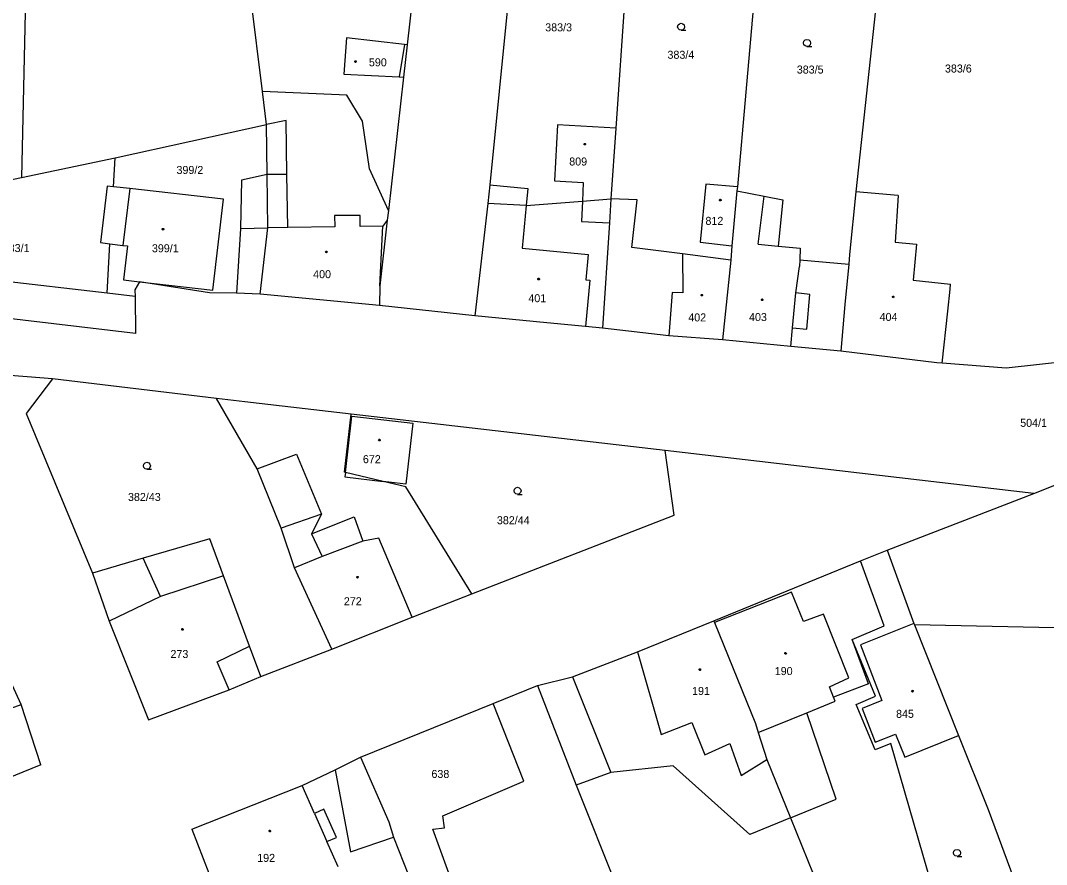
# Model space of a CAD drawing. Extents: x -757994 to -755874, y -1047691 to -1046119.
# Drawn here: x -757748.9 to -757640, y -1047070.2 to -1046980.7 of the extents above; entities that cross this region are included whole.
import ezdxf

# ---------------------------------------------------------------- set-up
doc = ezdxf.new("R2010")
doc.units = 0
doc.layers.add('katastrální mapa', color=7, linetype='Continuous')

msp = doc.modelspace()

# ---------------------------------------------------------------- linework, layer by layer
at = {"layer": 'katastrální mapa'}
for p, q in [((-757746.63, -1046900.81), (-757748.84, -1046997.32)), ((-757723.24, -1046988.2), (-757726.54, -1046961.83)), ((-757705.82, -1046964.85), (-757707.89, -1046983.24)), ((-757695.92, -1046966.36), (-757699.11, -1046998.09)), ((-757684.03, -1046967.9), (-757685.73, -1046992.09)), ((-757670.33, -1046970.08), (-757672.82, -1046998.32)), ((-757657.21, -1046970.65), (-757660.23, -1046998.82)), ((-757714.32, -1046982.5), (-757714.61, -1046986.34)), ((-757708.17, -1046983.21), (-757714.32, -1046982.5)), ((-757708.17, -1046983.21), (-757708.74, -1046986.64)), ((-757707.89, -1046983.24), (-757708.28, -1046986.66)), ((-757707.89, -1046983.24), (-757708.17, -1046983.21)), ((-757714.61, -1046986.34), (-757708.74, -1046986.64)), ((-757708.28, -1046986.66), (-757709.87, -1047000.8)), ((-757708.74, -1046986.64), (-757708.28, -1046986.66)), ((-757714.27, -1046988.59), (-757723.24, -1046988.2)), ((-757722.81, -1046991.67), (-757723.24, -1046988.2)), ((-757712.62, -1046991.35), (-757714.27, -1046988.59)), ((-757720.71, -1046991.28), (-757722.81, -1046991.67)), ((-757720.64, -1046996.98), (-757720.71, -1046991.28)), ((-757738.88, -1046995.22), (-757722.81, -1046991.67)), ((-757722.74, -1046997.01), (-757722.81, -1046991.67)), ((-757711.86, -1046996.41), (-757712.62, -1046991.35)), ((-757691.91, -1046991.73), (-757692.25, -1046997.66)), ((-757685.73, -1046992.09), (-757691.91, -1046991.73)), ((-757685.73, -1046992.09), (-757686.25, -1046999.57)), ((-757748.84, -1046997.32), (-757738.88, -1046995.22)), ((-757739.07, -1046998.31), (-757738.88, -1046995.22)), ((-757709.87, -1047000.8), (-757711.86, -1046996.41)), ((-757768.4, -1047001.45), (-757748.84, -1046997.32)), ((-757725.46, -1046997.59), (-757725.56, -1047002.71)), ((-757722.74, -1046997.01), (-757725.46, -1046997.59)), ((-757720.64, -1046996.98), (-757722.74, -1046997.01)), ((-757722.66, -1047002.66), (-757722.74, -1046997.01)), ((-757720.56, -1047002.63), (-757720.64, -1046996.98)), ((-757692.25, -1046997.66), (-757689.18, -1046997.84)), ((-757739.72, -1046998.25), (-757740.43, -1047004.2)), ((-757739.07, -1046998.31), (-757739.72, -1046998.25)), ((-757737.34, -1046998.49), (-757739.07, -1046998.31)), ((-757737.34, -1046998.49), (-757738.06, -1047004.52)), ((-757727.39, -1046999.6), (-757737.34, -1046998.49)), ((-757699.11, -1046998.09), (-757699.31, -1047000.09)), ((-757699.11, -1046998.09), (-757695.06, -1046998.49)), ((-757695.06, -1046998.49), (-757695.23, -1047000.28)), ((-757689.18, -1046997.84), (-757689.27, -1046999.81)), ((-757676.17, -1046998.03), (-757676.76, -1047004.18)), ((-757672.82, -1046998.32), (-757676.17, -1046998.03)), ((-757672.86, -1046998.74), (-757673.39, -1047004.55)), ((-757672.82, -1046998.32), (-757672.86, -1046998.74)), ((-757672.86, -1046998.74), (-757669.97, -1046999.3)), ((-757660.23, -1046998.82), (-757660.91, -1047005.48)), ((-757655.74, -1046999.21), (-757660.23, -1046998.82)), ((-757728.51, -1047009.26), (-757727.39, -1046999.6)), ((-757695.23, -1047000.28), (-757689.27, -1046999.81)), ((-757689.27, -1046999.81), (-757689.37, -1047001.98)), ((-757689.27, -1046999.81), (-757686.25, -1046999.57)), ((-757686.25, -1046999.57), (-757686.41, -1047002.11)), ((-757683.45, -1046999.68), (-757686.25, -1046999.57)), ((-757684.02, -1047004.74), (-757683.45, -1046999.68)), ((-757670.62, -1047004.39), (-757669.97, -1046999.3)), ((-757669.97, -1046999.3), (-757668.01, -1046999.68)), ((-757668.01, -1046999.68), (-757668.49, -1047004.59)), ((-757655.74, -1046999.21), (-757656.08, -1047004.16)), ((-757709.87, -1047000.8), (-757709.99, -1047001.84)), ((-757699.31, -1047000.09), (-757700.69, -1047012.01)), ((-757695.23, -1047000.28), (-757699.31, -1047000.09)), ((-757695.23, -1047000.28), (-757695.67, -1047004.81)), ((-757712.88, -1047001.33), (-757715.58, -1047001.36)), ((-757715.58, -1047001.36), (-757715.56, -1047002.56)), ((-757712.86, -1047002.53), (-757712.88, -1047001.33)), ((-757709.99, -1047001.84), (-757710.77, -1047008.8)), ((-757709.99, -1047001.84), (-757710.46, -1047002.49)), ((-757689.37, -1047001.98), (-757686.41, -1047002.11)), ((-757686.41, -1047002.11), (-757687.13, -1047013.32)), ((-757725.56, -1047002.71), (-757726, -1047009.6)), ((-757725.56, -1047002.71), (-757722.66, -1047002.66)), ((-757723.5, -1047009.7), (-757722.66, -1047002.66)), ((-757720.56, -1047002.63), (-757722.66, -1047002.66)), ((-757715.56, -1047002.56), (-757720.56, -1047002.63)), ((-757710.46, -1047002.49), (-757712.86, -1047002.53)), ((-757710.77, -1047008.8), (-757710.46, -1047002.49)), ((-757740.43, -1047004.2), (-757739.43, -1047004.34)), ((-757739.74, -1047009.6), (-757739.43, -1047004.34)), ((-757739.43, -1047004.34), (-757738.06, -1047004.52)), ((-757676.76, -1047004.18), (-757673.39, -1047004.55)), ((-757656.08, -1047004.16), (-757653.8, -1047004.38)), ((-757738.06, -1047004.52), (-757737.58, -1047004.58)), ((-757737.58, -1047004.58), (-757738.01, -1047008.18)), ((-757695.67, -1047004.81), (-757688.65, -1047005.49)), ((-757678.63, -1047005.43), (-757684.02, -1047004.74)), ((-757673.53, -1047006.08), (-757678.63, -1047005.43)), ((-757678.63, -1047005.43), (-757678.61, -1047009.56)), ((-757673.39, -1047004.55), (-757673.53, -1047006.08)), ((-757670.62, -1047004.39), (-757668.49, -1047004.59)), ((-757668.49, -1047004.59), (-757666.14, -1047004.82)), ((-757666.14, -1047004.82), (-757666.19, -1047006.07)), ((-757653.8, -1047004.38), (-757654.14, -1047008.21)), ((-757739.74, -1047009.6), (-757768.44, -1047006.28)), ((-757688.65, -1047005.49), (-757688.91, -1047008.17)), ((-757673.53, -1047006.08), (-757674.39, -1047014.55)), ((-757666.19, -1047006.07), (-757666.21, -1047006.75)), ((-757666.19, -1047006.07), (-757661, -1047006.5)), ((-757661, -1047006.5), (-757661.4, -1047010.78)), ((-757660.91, -1047005.48), (-757661, -1047006.5)), ((-757666.6, -1047009.57), (-757666.21, -1047006.75)), ((-757738.01, -1047008.18), (-757736.29, -1047008.38)), ((-757736.29, -1047008.38), (-757736.78, -1047009.23)), ((-757728.87, -1047009.55), (-757736.29, -1047008.38)), ((-757736.29, -1047008.38), (-757728.51, -1047009.26)), ((-757688.47, -1047008.22), (-757688.94, -1047013.14)), ((-757688.91, -1047008.17), (-757688.47, -1047008.22)), ((-757654.14, -1047008.21), (-757650.18, -1047008.64)), ((-757650.23, -1047009.15), (-757650.18, -1047008.64)), ((-757736.76, -1047009.95), (-757739.74, -1047009.6)), ((-757736.78, -1047009.23), (-757736.76, -1047009.95)), ((-757726, -1047009.6), (-757728.87, -1047009.55)), ((-757723.5, -1047009.7), (-757726, -1047009.6)), ((-757710.8, -1047010.9), (-757723.5, -1047009.7)), ((-757710.77, -1047008.8), (-757710.8, -1047010.9)), ((-757679.73, -1047009.53), (-757680.09, -1047014.12)), ((-757678.61, -1047009.56), (-757679.73, -1047009.53)), ((-757666.96, -1047013.26), (-757666.6, -1047009.57)), ((-757665.11, -1047009.72), (-757666.6, -1047009.57)), ((-757665.46, -1047013.4), (-757665.11, -1047009.72)), ((-757650.47, -1047011.51), (-757650.23, -1047009.15)), ((-757736.72, -1047013.89), (-757768.56, -1047010.11)), ((-757736.76, -1047009.95), (-757736.72, -1047013.89)), ((-757661.4, -1047010.78), (-757661.85, -1047015.76)), ((-757700.69, -1047012.01), (-757710.8, -1047010.9)), ((-757651.06, -1047017.02), (-757650.47, -1047011.51)), ((-757693.05, -1047012.74), (-757700.69, -1047012.01)), ((-757688.94, -1047013.14), (-757693.05, -1047012.74)), ((-757687.13, -1047013.32), (-757688.94, -1047013.14)), ((-757680.09, -1047014.12), (-757687.13, -1047013.32)), ((-757674.39, -1047014.55), (-757680.09, -1047014.12)), ((-757667.15, -1047015.25), (-757666.96, -1047013.26)), ((-757666.96, -1047013.26), (-757665.46, -1047013.4)), ((-757667.15, -1047015.25), (-757674.39, -1047014.55)), ((-757661.85, -1047015.76), (-757667.15, -1047015.25)), ((-757651.63, -1047016.98), (-757661.85, -1047015.76)), ((-757745.55, -1047018.69), (-757763.54, -1047017.3)), ((-757651.06, -1047017.02), (-757651.63, -1047016.98)), ((-757644.28, -1047017.56), (-757651.06, -1047017.02)), ((-757637.31, -1047016.79), (-757644.28, -1047017.56)), ((-757745.55, -1047018.69), (-757748.32, -1047022.35)), ((-757728.12, -1047020.77), (-757745.55, -1047018.69)), ((-757725.12, -1047021.13), (-757728.12, -1047020.77)), ((-757723.82, -1047028.23), (-757728.12, -1047020.77)), ((-757713.82, -1047022.44), (-757725.12, -1047021.13)), ((-757748.32, -1047022.35), (-757741.28, -1047039.31)), ((-757714.53, -1047028.6), (-757713.82, -1047022.44)), ((-757714.43, -1047028.62), (-757713.74, -1047022.64)), ((-757680.49, -1047026.3), (-757713.82, -1047022.44)), ((-757713.74, -1047022.64), (-757707.28, -1047023.39)), ((-757707.28, -1047023.39), (-757708.03, -1047029.85)), ((-757723.82, -1047028.23), (-757719.63, -1047026.67)), ((-757719.63, -1047026.67), (-757716.98, -1047033.05)), ((-757641.33, -1047030.84), (-757680.49, -1047026.3)), ((-757679.53, -1047033.16), (-757680.49, -1047026.3)), ((-757721.24, -1047034.52), (-757723.82, -1047028.23)), ((-757714.43, -1047028.62), (-757714.53, -1047028.6)), ((-757714.43, -1047028.62), (-757714.49, -1047029.1)), ((-757714.49, -1047029.1), (-757710.41, -1047029.57)), ((-757710.41, -1047029.57), (-757714.43, -1047028.62)), ((-757708.03, -1047029.85), (-757710.41, -1047029.57)), ((-757708.01, -1047030.14), (-757710.41, -1047029.57)), ((-757701, -1047041.51), (-757708.01, -1047030.14)), ((-757641.33, -1047030.84), (-757638.57, -1047029.77)), ((-757656.93, -1047036.87), (-757641.33, -1047030.84)), ((-757716.98, -1047033.05), (-757721.24, -1047034.52)), ((-757716.98, -1047033.05), (-757718.04, -1047035.13)), ((-757718.04, -1047035.13), (-757713.5, -1047033.32)), ((-757713.5, -1047033.32), (-757712.57, -1047035.93)), ((-757701, -1047041.51), (-757679.53, -1047033.16)), ((-757719.84, -1047038.74), (-757721.24, -1047034.52)), ((-757728.84, -1047035.66), (-757735.9, -1047037.73)), ((-757727.38, -1047039.61), (-757728.84, -1047035.66)), ((-757718.04, -1047035.13), (-757716.89, -1047037.56)), ((-757712.57, -1047035.93), (-757716.89, -1047037.56)), ((-757710.9, -1047035.59), (-757712.57, -1047035.93)), ((-757707.36, -1047043.98), (-757710.9, -1047035.59)), ((-757659.75, -1047038.02), (-757656.93, -1047036.87)), ((-757656.93, -1047036.87), (-757654.07, -1047044.65)), ((-757735.9, -1047037.73), (-757741.28, -1047039.31)), ((-757734.07, -1047041.79), (-757735.9, -1047037.73)), ((-757716.89, -1047037.56), (-757719.84, -1047038.74)), ((-757675.32, -1047044.38), (-757659.75, -1047038.02)), ((-757657.23, -1047044.9), (-757659.75, -1047038.02)), ((-757715.86, -1047047.38), (-757719.84, -1047038.74)), ((-757741.28, -1047039.31), (-757739.53, -1047044.41)), ((-757727.38, -1047039.61), (-757734.07, -1047041.79)), ((-757724.62, -1047047.08), (-757727.38, -1047039.61)), ((-757667.08, -1047041.32), (-757675.25, -1047044.55)), ((-757665.8, -1047044.46), (-757667.08, -1047041.32)), ((-757734.07, -1047041.79), (-757739.53, -1047044.41)), ((-757707.36, -1047043.98), (-757701, -1047041.51)), ((-757739.53, -1047044.41), (-757735.34, -1047054.87)), ((-757715.86, -1047047.38), (-757707.36, -1047043.98)), ((-757683.43, -1047047.68), (-757675.32, -1047044.38)), ((-757675.32, -1047044.38), (-757675.25, -1047044.55)), ((-757675.25, -1047044.55), (-757670.91, -1047055.28)), ((-757663.69, -1047043.66), (-757665.8, -1047044.46)), ((-757660.97, -1047050.44), (-757663.69, -1047043.66)), ((-757654.07, -1047044.65), (-757659.75, -1047046.93)), ((-757654.07, -1047044.65), (-757654.02, -1047044.79)), ((-757660.62, -1047046.36), (-757657.23, -1047044.9)), ((-757622.16, -1047045.46), (-757654.02, -1047044.79)), ((-757654.02, -1047044.79), (-757649.33, -1047056.56)), ((-757658.14, -1047052.38), (-757660.62, -1047046.36)), ((-757658.9, -1047051.07), (-757660.62, -1047046.36)), ((-757748.85, -1047053.27), (-757751.56, -1047047.49)), ((-757728.06, -1047048.74), (-757724.62, -1047047.08)), ((-757723.43, -1047050.29), (-757724.62, -1047047.08)), ((-757723.43, -1047050.29), (-757715.86, -1047047.38)), ((-757690.34, -1047050.32), (-757683.43, -1047047.68)), ((-757683.43, -1047047.68), (-757680.92, -1047056.45)), ((-757659.75, -1047046.93), (-757657.47, -1047052.82)), ((-757726.76, -1047051.7), (-757728.06, -1047048.74)), ((-757726.76, -1047051.7), (-757723.43, -1047050.29)), ((-757694.04, -1047051.24), (-757690.34, -1047050.32)), ((-757690.34, -1047050.32), (-757686.25, -1047060.48)), ((-757663.05, -1047051.37), (-757660.97, -1047050.44)), ((-757658.9, -1047051.07), (-757662.62, -1047052.48)), ((-757735.34, -1047054.87), (-757726.76, -1047051.7)), ((-757698.74, -1047053.14), (-757694.04, -1047051.24)), ((-757694.04, -1047051.24), (-757689.95, -1047061.83)), ((-757662.62, -1047052.48), (-757663.05, -1047051.37)), ((-757753.37, -1047054.87), (-757748.85, -1047053.27)), ((-757746.77, -1047059.67), (-757748.85, -1047053.27)), ((-757712.85, -1047058.83), (-757698.74, -1047053.14)), ((-757695.5, -1047061.4), (-757698.74, -1047053.14)), ((-757665.44, -1047054.13), (-757662.45, -1047052.91)), ((-757662.45, -1047052.91), (-757662.62, -1047052.48)), ((-757660.2, -1047053.24), (-757658.14, -1047052.38)), ((-757658.18, -1047058.08), (-757660.2, -1047053.24)), ((-757657.47, -1047052.82), (-757659.56, -1047053.69)), ((-757670.6, -1047056.24), (-757665.44, -1047054.13)), ((-757662.34, -1047063.3), (-757665.44, -1047054.13)), ((-757659.56, -1047053.69), (-757658.18, -1047057.24)), ((-757680.92, -1047056.45), (-757677.65, -1047055.16)), ((-757677.65, -1047055.16), (-757676.29, -1047058.58)), ((-757670.91, -1047055.28), (-757670.6, -1047056.24)), ((-757670.6, -1047056.24), (-757669.68, -1047059.08)), ((-757658.18, -1047057.24), (-757656.04, -1047056.39)), ((-757656.04, -1047056.39), (-757655.04, -1047058.83)), ((-757655.04, -1047058.83), (-757649.33, -1047056.56)), ((-757649.33, -1047056.56), (-757646.2, -1047064.4)), ((-757676.29, -1047058.58), (-757673.62, -1047057.41)), ((-757673.62, -1047057.41), (-757672.4, -1047060.8)), ((-757656.53, -1047057.4), (-757658.18, -1047058.08)), ((-757647.27, -1047089.5), (-757656.53, -1047057.4)), ((-757746.77, -1047059.67), (-757760.07, -1047065.06)), ((-757715.54, -1047060.2), (-757712.85, -1047058.83)), ((-757712.85, -1047058.83), (-757709.84, -1047065.71)), ((-757679.65, -1047059.77), (-757686.25, -1047060.48)), ((-757671.5, -1047067.07), (-757679.65, -1047059.77)), ((-757672.4, -1047060.8), (-757669.68, -1047059.08)), ((-757669.68, -1047059.08), (-757667.17, -1047065.29)), ((-757719.04, -1047061.86), (-757715.54, -1047060.2)), ((-757715.54, -1047060.2), (-757713.9, -1047068.9)), ((-757686.25, -1047060.48), (-757689.95, -1047061.83)), ((-757730.75, -1047066.49), (-757719.04, -1047061.86)), ((-757717.72, -1047064.82), (-757719.04, -1047061.86)), ((-757704.1, -1047065.06), (-757695.5, -1047061.4)), ((-757689.95, -1047061.83), (-757674.85, -1047099.28)), ((-757667.17, -1047065.29), (-757662.34, -1047063.3)), ((-757716.72, -1047064.37), (-757717.72, -1047064.82)), ((-757717.72, -1047064.82), (-757716.4, -1047067.8)), ((-757715.39, -1047067.36), (-757716.72, -1047064.37)), ((-757703.91, -1047066.35), (-757704.1, -1047065.06)), ((-757667.17, -1047065.29), (-757671.5, -1047067.07)), ((-757667.17, -1047065.29), (-757656.22, -1047092.42)), ((-757646.2, -1047064.4), (-757643.09, -1047072.73)), ((-757709.84, -1047065.71), (-757709.33, -1047067.33)), ((-757705.17, -1047066.49), (-757703.91, -1047066.35)), ((-757730.75, -1047066.49), (-757727.6, -1047074.6)), ((-757716.4, -1047067.8), (-757715.39, -1047067.36)), ((-757713.9, -1047068.9), (-757709.33, -1047067.33)), ((-757709.33, -1047067.33), (-757706.55, -1047074.4)), ((-757702.67, -1047073.29), (-757705.17, -1047066.49)), ((-757715.2, -1047070.5), (-757716.4, -1047067.8))]:
    msp.add_line(p, q, dxfattribs=at)
for points in [[(-757678.79, -1046981.68), (-757678.98, -1046981.63), (-757679.11, -1046981.5), (-757679.17, -1046981.31), (-757679.11, -1046981.12), (-757678.98, -1046980.99), (-757678.8, -1046980.94), (-757678.61, -1046980.99), (-757678.48, -1046981.12), (-757678.43, -1046981.32), (-757678.48, -1046981.51), (-757678.61, -1046981.64), (-757678.8, -1046981.69), (-757678.3, -1046981.69)], [(-757665.42, -1046983.4), (-757665.61, -1046983.35), (-757665.75, -1046983.22), (-757665.8, -1046983.03), (-757665.75, -1046982.85), (-757665.61, -1046982.71), (-757665.43, -1046982.66), (-757665.24, -1046982.71), (-757665.1, -1046982.85), (-757665.06, -1046983.04), (-757665.1, -1046983.23), (-757665.24, -1046983.36), (-757665.43, -1046983.41), (-757664.93, -1046983.41)], [(-757735.5, -1047028.28), (-757735.69, -1047028.23), (-757735.83, -1047028.1), (-757735.88, -1047027.91), (-757735.83, -1047027.73), (-757735.69, -1047027.59), (-757735.51, -1047027.54), (-757735.32, -1047027.59), (-757735.19, -1047027.73), (-757735.14, -1047027.92), (-757735.19, -1047028.11), (-757735.32, -1047028.24), (-757735.51, -1047028.29), (-757735.01, -1047028.29)], [(-757696.15, -1047030.94), (-757696.34, -1047030.89), (-757696.48, -1047030.75), (-757696.53, -1047030.57), (-757696.48, -1047030.39), (-757696.34, -1047030.25), (-757696.16, -1047030.2), (-757695.97, -1047030.25), (-757695.84, -1047030.39), (-757695.79, -1047030.58), (-757695.84, -1047030.76), (-757695.97, -1047030.9), (-757696.16, -1047030.95), (-757695.66, -1047030.95)], [(-757649.49, -1047069.37), (-757649.68, -1047069.32), (-757649.82, -1047069.19), (-757649.86, -1047069), (-757649.82, -1047068.82), (-757649.68, -1047068.68), (-757649.49, -1047068.63), (-757649.31, -1047068.68), (-757649.18, -1047068.82), (-757649.12, -1047069.01), (-757649.18, -1047069.2), (-757649.31, -1047069.33), (-757649.5, -1047069.38), (-757649, -1047069.38)]]:
    msp.add_lwpolyline(points, dxfattribs=at)
for points in [[(-757713.36, -1046984.93), (-757713.31, -1046984.94), (-757713.28, -1046984.98), (-757713.27, -1046985.01), (-757713.28, -1046985.05), (-757713.33, -1046985.09), (-757713.36, -1046985.1), (-757713.41, -1046985.08), (-757713.44, -1046985.05), (-757713.45, -1046985.01), (-757713.44, -1046984.97), (-757713.4, -1046984.93)], [(-757689.02, -1046993.69), (-757688.97, -1046993.7), (-757688.95, -1046993.74), (-757688.94, -1046993.77), (-757688.95, -1046993.82), (-757688.99, -1046993.85), (-757689.02, -1046993.86), (-757689.07, -1046993.84), (-757689.1, -1046993.81), (-757689.1, -1046993.77), (-757689.1, -1046993.73), (-757689.05, -1046993.69)], [(-757674.63, -1046999.62), (-757674.58, -1046999.64), (-757674.55, -1046999.68), (-757674.54, -1046999.71), (-757674.55, -1046999.75), (-757674.6, -1046999.79), (-757674.63, -1046999.79), (-757674.68, -1046999.78), (-757674.71, -1046999.75), (-757674.72, -1046999.71), (-757674.71, -1046999.67), (-757674.67, -1046999.63)], [(-757733.8, -1047002.72), (-757733.75, -1047002.73), (-757733.73, -1047002.77), (-757733.72, -1047002.8), (-757733.73, -1047002.85), (-757733.77, -1047002.88), (-757733.8, -1047002.89), (-757733.85, -1047002.87), (-757733.88, -1047002.84), (-757733.89, -1047002.8), (-757733.88, -1047002.76), (-757733.84, -1047002.72)], [(-757716.46, -1047005.14), (-757716.41, -1047005.15), (-757716.39, -1047005.19), (-757716.38, -1047005.22), (-757716.39, -1047005.26), (-757716.43, -1047005.3), (-757716.46, -1047005.3), (-757716.5, -1047005.29), (-757716.53, -1047005.26), (-757716.54, -1047005.22), (-757716.53, -1047005.18), (-757716.49, -1047005.14)], [(-757693.91, -1047008), (-757693.86, -1047008.01), (-757693.84, -1047008.06), (-757693.83, -1047008.09), (-757693.84, -1047008.14), (-757693.88, -1047008.17), (-757693.91, -1047008.18), (-757693.96, -1047008.16), (-757693.99, -1047008.13), (-757694, -1047008.09), (-757693.99, -1047008.04), (-757693.95, -1047008.01)], [(-757676.6, -1047009.72), (-757676.55, -1047009.73), (-757676.52, -1047009.77), (-757676.51, -1047009.8), (-757676.52, -1047009.85), (-757676.57, -1047009.88), (-757676.6, -1047009.89), (-757676.65, -1047009.87), (-757676.68, -1047009.84), (-757676.69, -1047009.8), (-757676.68, -1047009.76), (-757676.64, -1047009.72)], [(-757670.19, -1047010.21), (-757670.14, -1047010.22), (-757670.11, -1047010.26), (-757670.1, -1047010.29), (-757670.11, -1047010.34), (-757670.16, -1047010.37), (-757670.19, -1047010.38), (-757670.23, -1047010.36), (-757670.26, -1047010.33), (-757670.27, -1047010.29), (-757670.26, -1047010.25), (-757670.22, -1047010.21)], [(-757656.26, -1047009.91), (-757656.21, -1047009.92), (-757656.19, -1047009.96), (-757656.18, -1047009.99), (-757656.19, -1047010.03), (-757656.23, -1047010.07), (-757656.26, -1047010.08), (-757656.3, -1047010.06), (-757656.34, -1047010.03), (-757656.35, -1047009.99), (-757656.34, -1047009.95), (-757656.29, -1047009.91)], [(-757710.82, -1047025.1), (-757710.77, -1047025.11), (-757710.74, -1047025.15), (-757710.73, -1047025.18), (-757710.74, -1047025.23), (-757710.78, -1047025.26), (-757710.82, -1047025.27), (-757710.86, -1047025.25), (-757710.9, -1047025.22), (-757710.91, -1047025.18), (-757710.9, -1047025.14), (-757710.85, -1047025.1)], [(-757713.14, -1047039.66), (-757713.09, -1047039.67), (-757713.07, -1047039.71), (-757713.05, -1047039.74), (-757713.07, -1047039.78), (-757713.1, -1047039.82), (-757713.14, -1047039.83), (-757713.19, -1047039.81), (-757713.22, -1047039.78), (-757713.23, -1047039.74), (-757713.22, -1047039.7), (-757713.18, -1047039.66)], [(-757731.73, -1047045.2), (-757731.68, -1047045.21), (-757731.66, -1047045.25), (-757731.65, -1047045.28), (-757731.66, -1047045.33), (-757731.7, -1047045.36), (-757731.73, -1047045.37), (-757731.77, -1047045.35), (-757731.8, -1047045.32), (-757731.82, -1047045.28), (-757731.8, -1047045.24), (-757731.76, -1047045.2)], [(-757667.71, -1047047.73), (-757667.66, -1047047.74), (-757667.64, -1047047.79), (-757667.62, -1047047.82), (-757667.64, -1047047.87), (-757667.68, -1047047.9), (-757667.71, -1047047.91), (-757667.75, -1047047.89), (-757667.78, -1047047.86), (-757667.79, -1047047.82), (-757667.78, -1047047.77), (-757667.74, -1047047.74)], [(-757676.8, -1047049.47), (-757676.75, -1047049.48), (-757676.73, -1047049.52), (-757676.72, -1047049.55), (-757676.73, -1047049.6), (-757676.77, -1047049.63), (-757676.8, -1047049.64), (-757676.85, -1047049.62), (-757676.88, -1047049.59), (-757676.89, -1047049.55), (-757676.88, -1047049.51), (-757676.84, -1047049.47)], [(-757654.21, -1047051.75), (-757654.16, -1047051.76), (-757654.14, -1047051.81), (-757654.12, -1047051.84), (-757654.14, -1047051.89), (-757654.18, -1047051.92), (-757654.21, -1047051.93), (-757654.25, -1047051.91), (-757654.28, -1047051.88), (-757654.29, -1047051.84), (-757654.28, -1047051.79), (-757654.24, -1047051.76)], [(-757722.46, -1047066.6), (-757722.41, -1047066.61), (-757722.39, -1047066.65), (-757722.38, -1047066.68), (-757722.39, -1047066.73), (-757722.43, -1047066.76), (-757722.46, -1047066.77), (-757722.5, -1047066.75), (-757722.53, -1047066.72), (-757722.54, -1047066.68), (-757722.53, -1047066.64), (-757722.49, -1047066.6)]]:
    msp.add_lwpolyline(points, close=True, dxfattribs=at)

# ---------------------------------------------------------------- texts
for s, p in [('383/3', (-757693.22, -1046981.8)), ('590', (-757711.94, -1046985.51)), ('383/4', (-757680.24, -1046984.71)), ('383/5', (-757666.51, -1046986.28)), ('383/6', (-757650.78, -1046986.17)), ('809', (-757690.67, -1046996.04)), ('399/2', (-757732.37, -1046996.94)), ('812', (-757676.21, -1047002.34)), ('383/1', (-757750.82, -1047005.23)), ('399/1', (-757734.98, -1047005.25)), ('400', (-757717.86, -1047008)), ('401', (-757695.01, -1047010.55)), ('402', (-757678.03, -1047012.59)), ('403', (-757671.58, -1047012.55)), ('404', (-757657.72, -1047012.54)), ('504/1', (-757642.79, -1047023.78)), ('672', (-757712.58, -1047027.64)), ('382/43', (-757737.52, -1047031.65)), ('382/44', (-757698.35, -1047034.12)), ('272', (-757714.6, -1047042.72)), ('273', (-757733.01, -1047048.32)), ('190', (-757668.85, -1047050.13)), ('191', (-757677.63, -1047052.24)), ('845', (-757655.97, -1047054.67)), ('638', (-757705.3, -1047061.05)), ('192', (-757723.8, -1047069.96))]:
    msp.add_text(s, height=0.85, dxfattribs=at).set_placement(p)

doc.saveas('drawing.dxf')
